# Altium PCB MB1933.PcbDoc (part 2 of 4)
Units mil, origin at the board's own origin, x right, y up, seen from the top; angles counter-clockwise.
Board outline 2755.91 x 3937.01 mil, 4 copper layers (Top Layer, GND, POWER, Bottom Layer), stack 60.63 mil thick; 228 components, 185 nets, 918 pads, 786 vias.
Unrouted connection lines stored in the file: 160.
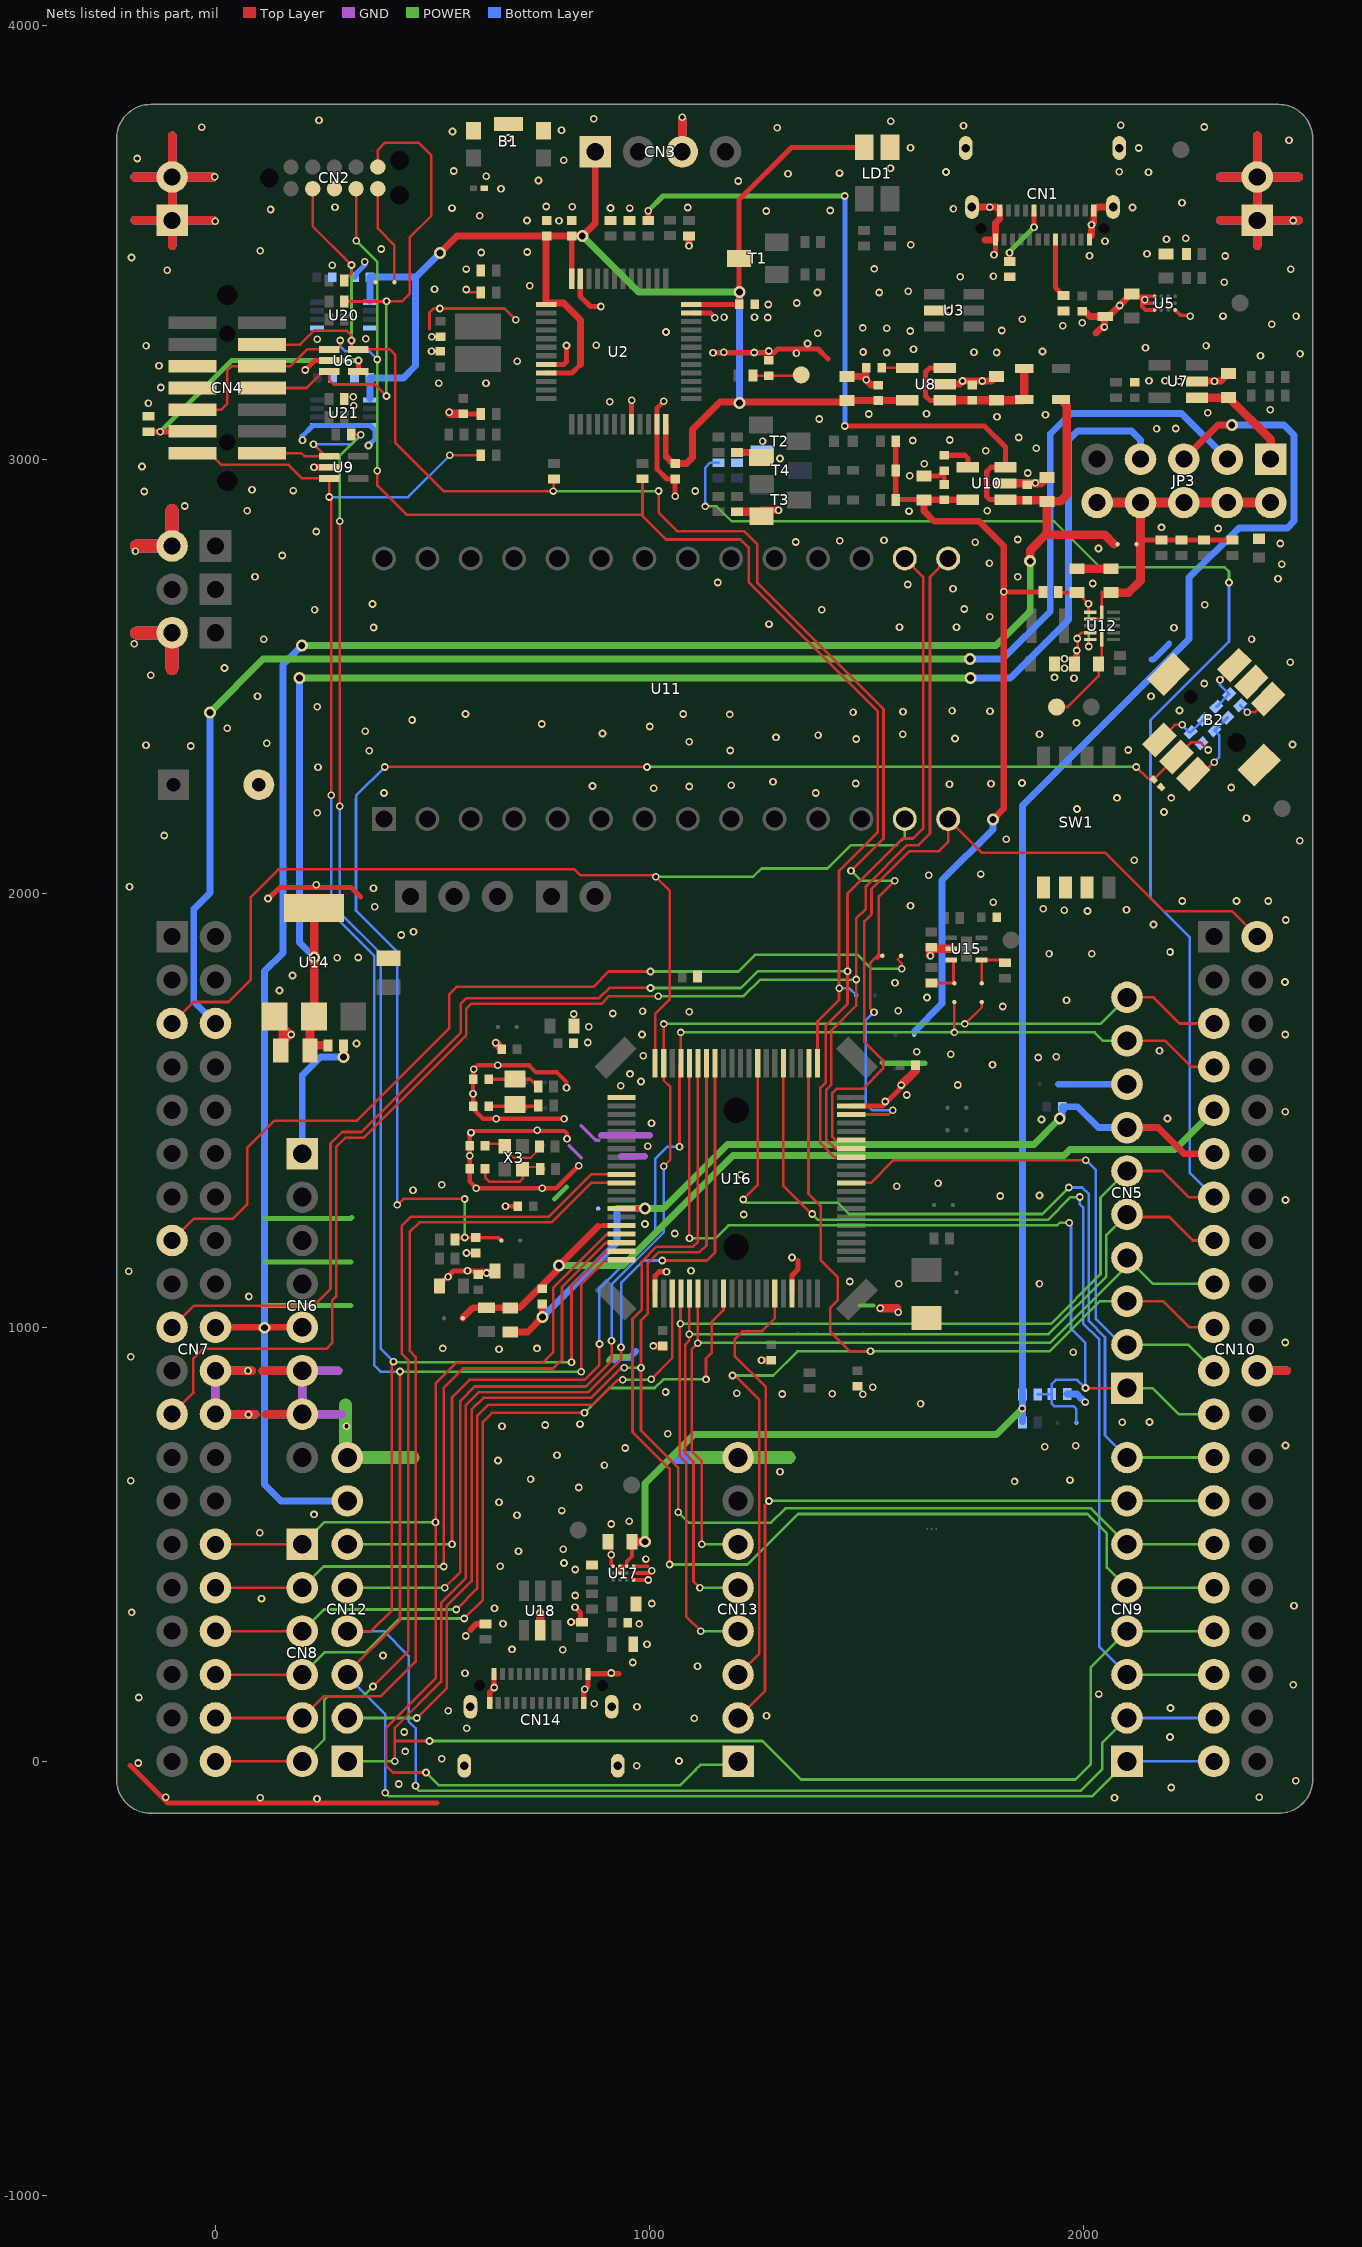
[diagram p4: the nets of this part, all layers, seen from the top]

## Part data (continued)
T1 T2 T3 T4: library part MCD-00073, "NPN Bipolar Transistor", Manufacturer="ON SEMICONDUCTOR", Manufacturer_Part_Number=BSR14, Package=SOT23
TP1 TP2 TP3 TP4 TP5 TP6: library part MCD-00074, "Test Point 1mm", Manufacturer=N/A, Manufacturer_HQ_COO=Unknown
TS1: library part MCD-01194, "-Touch Sensing button: diameter 10mm min,  active shield diameter 12mm min", Manufacturer=N/A, Manufacturer_Part_Number=Touch_sensing_Button
U1 U13: library part MCD-00170, "Diode, ESD TVS, 3V, 100nA, 8V, ST0201", Manufacturer=STMICROELECTRONICS, Manufacturer_HQ_COO=EU, Manufacturer_Part_Number=ESDALC6V1-1U2, Package=ST0201
U2: library part MCD-03056, "MCU, ARM Cortex-M3 32-bit, 128KB Flash, 20KB RAM, No Crypto", Manufacturer=STMICROELECTRONICS, Manufacturer_Part_Number=STM32F103CBT6, Package=LQFP48
U3 U18: library part MCD-00163, "Very low capacitance ESD protection", Manufacturer=STMICROELECTRONICS, Manufacturer_HQ_COO=EU
U4 U19: library part MCD-01207, "Diode, ESD TVS, 22V, 200nA, 25V8, QFN1610", Manufacturer=STMICROELECTRONICS, Manufacturer_HQ_COO=EU, Manufacturer_Part_Number=ESDA25P35-1U1M, Package=QFN1610
U5: library part MCD-03166, "Power switch, 28 V / 5 A  OVP with Low On-resistance, Integrated TVS", Manufacturer="ON SEMICONDUCTOR", Package=WLCSP-12
U6 U9: library part MCD-00136, "Diode, ESD Transil, 3V, 1uA, 7V2, SOT323-5L", Manufacturer=STMICROELECTRONICS, Manufacturer_HQ_COO=EU, Package=SOT323-5
U7: library part MCD-00083, "Enhanced single channel power switches with active low enable pin", Manufacturer=STMICROELECTRONICS, Manufacturer_HQ_COO=EU
U8 U10: library part MCD-00663, "LDO, 200mA, Low quiescent current very low noise LDO", Manufacturer=STMICROELECTRONICS, Manufacturer_HQ_COO=EU, Package=SOT23-5
U11: library part MCD-03134, "Segment LCD, 4 COM, 24 data, DIP28 package", Manufacturer=HZDSLCD, Package=DIP28
U12: library part MCD-03133, "400mA Nano-Quiescent Step down converter with Aux switch", Manufacturer=STMICROELECTRONICS, Manufacturer_Part_Number=ST1PS03AQTR, Package=TQFN12
U14: library part MCD-00088, "IC REG LDO 5V 0.8A SOT223", Manufacturer=STMICROELECTRONICS, Manufacturer_HQ_COO=EU, Package=SOT-223
U15: library part MCD-02159, "MEMS, Low-voltage, ultra-low-power, 0.5°C accuracy I2C/SMBus 3.0 temperature sensor", Manufacturer=STMICROELECTRONICS, Manufacturer_HQ_COO=EU, Package=UDFN-6
U16: library part MCD-03131, "Arm® Cortex®-M0+ 32-bit MCU,  256K Flash memory, with LQFP80 socket footprint (IC149-080-130-B5)", Manufacturer=STMICROELECTRONICS, Package=LQFP80
U17: library part MCD-03166, "Power switch, 28 V / 5 A  OVP with Low On-resistance, Integrated TVS", Manufacturer="ON SEMICONDUCTOR", Manufacturer_Part_Number=FPF3380UCX, Package=WLCSP-12
U20 U21: library part MCD-00264, "IC, 5 Dual-Bit Dual-Supply bus transceiver with configurable voltage translation and 3-State outputs", Manufacturer="TEXAS INSTRUMENTS", Package=VSSOP-8
X1: library part MCD-00092, "Crystal, 8MHz, 8pF, +/-20ppm, 500R, 3.2x2.5mm", Manufacturer=NDK, Manufacturer_Part_Number=NX3225GD-8MHZ-EXS00A-CG04874, Package=3.2x2.5mm
X2: library part MCD-01479, "Crystal, 32.768kHz, 6pF, +/-20ppm, 80K, 2.05x1.2mm", Manufacturer=NDK, Manufacturer_Part_Number=NX2012SA-32.768KHZ-EXS00A-MU00527, Package=2.05x1.2mm
X3: library part MCD-01036, "Crystal, 24MHz, 6pF, +/-20ppm, 80R, 2x1.6mm", Manufacturer=NDK, Manufacturer_Part_Number=NX2016SA-24MHZ-EXS00A-CS10820, Package=2x1.6mm

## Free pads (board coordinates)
  round 11.81 on Mech16 mask+1.97: 0(-227.95,-119.75) 0(-227.95,3817.26) 0(2527.96,-119.75) 0(2527.96,3817.26) 2(-96.85,2275)
  oval 31.5x55.12 on Top Paste mask+1.97: 0(573.23,-10.04) 0(587.4,125.79) 0(912.6,125.79) 0(926.77,-10.04) 0(1728.5,3716.77) 0(1742.68,3580.94) 0(2067.87,3580.94) 0(2082.05,3716.77)
  round 20 on Mech16: 1(136.26,-962.54) 1(2059.39,-962.54)

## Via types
v1: diameter 17.72, hole 9.84, Top Layer to Bottom Layer, tented both sides, 740 vias
v2: diameter 27.56, hole 15.75, Top Layer to Bottom Layer, tented both sides, 45 vias
v3: diameter 19.68, hole 11.81, Top Layer to Bottom Layer, tented both sides, 1 vias

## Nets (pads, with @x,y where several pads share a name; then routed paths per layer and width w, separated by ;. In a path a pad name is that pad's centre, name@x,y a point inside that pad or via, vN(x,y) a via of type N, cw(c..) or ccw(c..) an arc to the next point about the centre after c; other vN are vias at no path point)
3V3: C20.2 C22.2 R32.2 R36.2 R39.2 R44.1 SB14.1 U10.5 | length 1846
  Top Layer w11.81: R39.2@1567.33,2897.77 R39.2@1567.33,2906.68 ; R32.2@1567.33,3041.28 R39.2@1567.33,2906.68 ; C20.2@1632,2906.68 R39.2@1567.33,2906.68 ; v1(1816,2694.28) R44.1@1906.28,2694.28
  Top Layer w15.75: C20.2@1632,2906.04 1632,2880.84 1655.86,2856.98 1759.11,2856.98 1816,2800.09 v1(1816,2694.28) 1816,2195 v2(1791,2170) ; C20.2@1632,2906.68 U10.5@1733.22,2906.68
  Bottom Layer w15.75: 1610.15,1681.73 1674,1745.59 1674,2030 1791,2147 v2(1791,2170)
3V3_STLK: C1.1 C2.1 C6.1 C13.2 C16.2 C19.1 C54.2 C56.2 CN3.1 LD1.4 T1.3 U2.1 U2.9 U2.24 U2.36 U2.48 U8.5 U20.1 U21.1 | length 3861.4
  Top Layer w11.81: U2.9@761.68,3198.79 821.59,3198.79 840.56,3217.75 ; C1.1@761.68,3513.16 C1.1@762.8,3514.28 ; U2.48@820.73,3415.32 820.73,3514.02 C2.1@821,3514.28 ; U2.24@1037.27,3080.68 1037.27,3004.21 1051.51,2989.97 1057.12,2989.97 1039.67,3007.42 ; U2.36@1096.32,3356.27 C6.1@1206.73,3356.27 ; C6.1@1206.37,3357.78 1206.37,3597.74 1326.87,3718.23 LD1.4@1494.62,3718.23
  Top Layer w15.75: v2(516.96,3474.69) 556.55,3514.28 C1.1@762.8,3514.28 C2.1@821,3514.28 v2(845.06,3514.28) 874.96,3544.18 CN3.1@874.96,3708.25 ; C1.1@761.68,3513.16 761.68,3359.68 801.58,3359.68 840.56,3320.71 840.56,3217.75 ; C19.1@1058.96,2989.97 1085.51,2989.97 1098.83,3003.29 1098.83,3068.05 1162.1,3131.32 1455.16,3131.32 C13.2@1455.16,3135.57 1455.26,3135.47 U8.5@1593.45,3135.47
  POWER w15.75: v2(845.06,3514.28) 974.37,3384.98 v2(1206.9,3384.98)
  Bottom Layer w13.78: U20.1@356,3364.6 U20.1@356.21,3364.82
  Bottom Layer w15.75: U21.1@356,3139.41 356,3187.25 432.96,3187.25 460.93,3215.23 460.93,3419.35 ; U20.1@356,3364.6 356,3419.14 C54.2@356.21,3419.35 460.93,3419.35 ; U20.1@356.21,3364.82 356.21,3407.33 ; v2(516.96,3474.69) 461.61,3419.35 460.93,3419.35 ; v2(1206.9,3129.17) v2(1206.9,3384.98)
5V: C21.2 C23.2 CN6.5 CN7.20 CN12.7 D2.1 R4.2 SB2.2 U10.1 U10.3 | length 6505.5
  Top Layer w11.81: R4.2@997,3549.72 v1@997,3572.13 ; v1(1449.52,3076.61) 1771.17,3076.61 1819.84,3027.94 U10.3@1819.84,2981.48 1786.47,2981.48 1776.88,2971.89 1776.88,2914.01 1784.21,2906.68 U10.1@1819.84,2906.68
  Top Layer w15.75: CN7.20@0,1000 CN6.5@200,1000
  Top Layer w19.68: U10.1@1819.84,2906.68 1821.06,2905.46 1915.53,2905.46 C21.2@1918.19,2902.79 ; v2(1877,2765) 1877,2790.16 1912.49,2825.65 ; C21.2@1920.99,2900 C21.2@1918.19,2902.79 ; D2.1@1947.59,3137.73 1961,3124.32 1961,2917.68 1946.12,2902.79 C21.2@1918.19,2902.79 ; 2070.18,2804 2048.53,2825.65 1912.49,2825.65 ; 1912.49,2825.65 1915.56,2828.72 C21.2@1915.56,2902.79 C21.2@1918.19,2902.79
  POWER w11.81: v1(997.05,3572.18) 1031.01,3606.14 v1(1450.01,3606.14)
  POWER w15.75: v2(198.92,2570.41) 1798.53,2570.41 1877,2648.88 v2(1877,2765)
  Bottom Layer w11.81: v1(1450.01,3606.14) 1450.2,3605.94 v1@1450.2,3076.61
  Bottom Layer w15.75: v2(198.92,2570.41) 155.22,2526.71 155.22,1862.44 113.2,1820.41 v2(113.2,998.95) 113.2,638.03 151.23,600 CN12.7@300,600
5V_LP: C25.2 JP3.2 JP3.4 JP3.6 JP3.8 JP3.10 R40.1 R41.1 R42.1 R43.1 SB2.1 U12.2 U12.12 | length 959.8
  Top Layer w5.98: U12.2@2015.43,2631.75 2036.1,2631.75 2042,2637.65 U12.12@2042,2646.51 2042,2694.28
  Top Layer w11.81: 2132.28,2813.72 R40.1@2225,2813.72 R42.1@2343,2813.72
  Top Layer w19.68: C25.2@2058.96,2692.63 2103.71,2692.63 2131,2719.93 JP3.8@2131,2900
  Top Layer w23.62: JP3.10@2031,2900 JP3.8@2131,2900 JP3.6@2231,2900 JP3.4@2331,2900 JP3.2@2431,2900
5V_STLK: C11.2 JP3.1 U7.1 | length 255
  Top Layer w19.68: U7.1@2261.17,3141.57 C11.2@2333.51,3141.57 ; C11.2@2333.81,3142.36 2431,3045.17 JP3.1@2431,3000
5V_USB: C51.2 JP3.5 R72.2 R73.2 U17.A2 U17.A3 U17.B2 | length 4091.9
  Top Layer w8.66: U17.B2@931.77,433.75 U17.A2@931.77,449.5 U17.A3@947.52,449.5 947.52,460.52 959.56,472.56 C51.2@959.56,506
  Top Layer w15.75: JP3.5@2231,3000 2310,3079 v2(2341.34,3079)
  Top Layer w19.68: C51.2@959.56,506 v2(989.38,506)
  POWER w15.75: v2(989.38,506) 989.38,640.18 1102.2,753 1798.8,753 v1(1858.7,812.9)
  Bottom Layer w15.75: R73.2@1858.98,782.4 R72.2@1858.98,845.6 1858.98,2201.98 2243,2586 2243,2727 2357.73,2841.73 2469.19,2841.73 2485,2857.54 2485,3055.27 2461.27,3079 v2(2341.34,3079)
5V_VIN: C32.2 JP3.7 R51.1 U14.2 U14.4 | length 3499.3
  Top Layer w15.75: C32.2@217.72,1637.54 C32.2@217.72,1649.55 ; U14.2@217.72,1706.83 U14.2@227.07,1716.18
  Top Layer w19.68: U14.2@217.72,1706.83 217.72,1649.55 R51.1@258.77,1649.55 ; U14.2@227.07,1716.18 U14.4@227.07,1966.18
  POWER w15.75: v2(193.51,2496) v2(1739.57,2496)
  Bottom Layer w15.75: v2(193.51,2496) 193.51,1886.36 v2(227.57,1852.3) ; v2(1739.57,2496) 1831.1,2496 1965.07,2629.97 1965.07,3043.64 1985.93,3064.51 2110.74,3064.51 2131,3044.24 JP3.7@2131,3000
AGND: C46.1 C47.2 C58.1 CN5.7 CN10.11 SB21.2 U16.14 | length 2024.8
  Top Layer w12.6: U16.14@935.23,1273.62 v2@985.76,1273.62
  Top Layer w13.78: v2@985.76,1273.62 v2@989.38,1270
  Top Layer w15.75: C47.2@679,989.51 719.4,989.51 v2(753.75,1023.86) ; v2@753.26,1024.35 C46.1@753.26,1053.68 ; CN5.7@2100,1460 2171.44,1460 2231.44,1400 CN10.11@2300,1400
  POWER w15.75: v2(989.38,1273.6) 1031.66,1273.6 1179.39,1421.33 1885.33,1421.33 v2(1945,1481)
  Bottom Layer w15.75: v2(753.75,1023.86) 924.91,1195.02 SB21.2@924.91,1273.56 v2(989.38,1273.6) ; v2@988.8,1269.43 v2@989.38,1270 ; v2(1945,1481) 1950.72,1486.72 C58.1@1950.72,1508 ; C58.1@1950.72,1508.11 1985.93,1508.11 2034.04,1460 CN5.7@2100,1460
ARD_A0: CN7.30 CN8.1 CN13.1 U16.17 | length 2967.5
  Top Layer w5.98: CN7.30@0,500 CN8.1@200,500 ; v1(485,-25.59) 408.59,-25.59 393,-10 393,77.08 507,191.08 v1(507,551) 507,871 554,918 753.82,918 777.86,942.04 777.86,1090.88 901.54,1214.56 U16.17@935.23,1214.56
  POWER w5.98: CN8.1@200,500 251,551 v1(507,551) ; v1(485,-25.59) 514.22,-54.81 1071.19,-54.81 1106.15,-19.85 1106.15,-19.19 1117.19,-8.15 1200,-8.15 CN13.1@1200,0
ARD_A1: CN7.32 CN8.2 U16.18 | length 1605.6
  Top Layer w5.98: CN7.32@0,400 CN8.2@200,400 ; v1(526,449) 526,860.91 570.1,905.02 777.54,905.02 798.24,925.71 798.24,1092.9 900.22,1194.88 U16.18@935.23,1194.88
  POWER w5.98: CN8.2@201.34,398.66 CN8.2@200,400 249,449 v1(526,449)
ARD_A2: CN7.34 CN8.3 U16.23 | length 1697.7
  Top Layer w5.98: CN7.34@0,300 CN8.3@200,300 ; v1(555,350) 602.95,397.95 602.95,795.95 629.03,822.03 869.37,822.03 926.43,879.1 v1(938.1,879.1) ; v1(1003.7,880.2) 1052.22,928.72 1052.22,1077.62 U16.23@1052.36,1077.76
  POWER w5.98: CN8.3@200,300 250,350 v1@553,350 ; v1@555,348 v1@553,350 ; v1(555,350) v1@553,350 ; v1(938.1,879.1) 1002.6,879.1 v1(1003.7,880.2)
ARD_A3: CN7.36 CN8.4 U16.29 | length 1866.8
  Top Layer w5.98: CN7.36@0,200 CN8.4@200,200 ; v1(573,329.19) 616,372.19 616,781.9 637.1,803 v1(849.96,803) ; v1(1130,880) 1130,928.2 1143.06,941.26 1143.06,1011.94 1170.47,1039.34 U16.29@1170.47,1077.76
  POWER w5.98: CN8.4@200.45,199.55 CN8.4@200,200 251,251 346,251 424.19,329.19 v1(573,329.19) ; v1(849.96,803) 907.21,860.25 1011.95,860.25 1031.7,880 v1(1130,880)
ARD_A4: CN7.38 CN8.5 U16.11 | length 2044.4
  Top Layer w5.98: CN7.38@0,100 CN8.5@200,100 250.33,150.33 381.33,150.33 461.04,230.04 461.04,931.96 448,945 448,1220.35 469.57,1241.92 774.57,1241.92 865.32,1332.67 U16.11@935.23,1332.67
ARD_A5: CN7.40 CN8.6 U16.10 | length 2143.7
  Top Layer w5.98: CN7.40@0,0 CN8.6@200,0 ; v1(363,172.56) 443.85,253.41 443.85,925.15 428.85,940.15 428.85,1232.85 450.9,1254.9 767.87,1254.9 865.32,1352.36 U16.10@935.23,1352.36
  POWER w5.98: CN8.6@200,0 251,51 251,142 259.33,150.33 340.77,150.33 v1(363,172.56)
ARD_D0: CN4.13 CN9.1 CN10.39 CN12.3 R33.2 U9.3 U16.20 | length 6631.5
  Top Layer w5.98: CN4.13@-53,3014 -13.76,3014 13.39,2986.85 168.51,2986.85 199.7,2955.66 U9.3@262.5,2955.66 v1@262.5,2912.5 ; v1(267,2226) 262.04,2226 267,2230.96 267,2908 v1@262.5,2912.5 ; CN12.3@300,200 425,325 v1(425,898) ; v1(540,3009) R33.2@611.28,3009 ; v1@842.71,898 842.71,1099.47 898.74,1155.51 U16.20@935.23,1155.51 ; v1@262.5,2912.5 262.5,2911.47 262,2911.96 v1(262,2913) v1@262.5,2912.5
  POWER w5.98: v1(262,2913) 262.19,2913 v1@262.51,2912.68 ; v1(391,-72) 399.78,-80.78 425.78,-80.78 2019.22,-80.78 CN9.1@2100,0 ; v1(425,898) 842.5,898 v1@842.72,897.77
  Bottom Layer w5.98: v1@262.51,2912.68 443.68,2912.68 v1(540,3009) ; v1(267,2226) 267,1954 365.85,1855.15 365.85,912.15 380,898 v1(425,898) ; CN12.3@300,200 391,109 v1(391,-72) ; v1@842.72,897.77 v1(842.82,897.87) ; CN9.1@2100,0 CN10.39@2300,0
ARD_D1: CN4.14 CN9.2 CN10.37 CN12.4 R27.2 U9.1 U16.19 | length 6404.8
  Top Layer w5.98: CN4.14@107,3014 197.46,3014 204.62,3006.84 U9.1@253.44,3006.84 ; v1(225.88,3034.4) U9.1@253.44,3006.84 ; U9.1@262.5,3006.84 U9.1@253.44,3006.84 ; v1@286,2200.36 v1(286,2857) ; CN12.4@300,300 358,300 406.15,348.15 v1@406.15,921 ; R27.2@313.69,3057.22 314.77,3056.14 v1(334.85,3056.14) ; U16.19@935.23,1175.19 900.06,1175.19 820.24,1095.37 v1@820.24,919.92 ; v1@820.24,919.92 819.94,919.62 v1(820.24,919.62) v1@820.24,919.92
  POWER w5.98: v1(286,2857) 286,3007.29 v1(334.85,3056.14) ; v1(410,921) 411.38,919.62 v1(820.24,919.62) ; v1(461,-56) 461,-60 468.79,-67.79 1993.21,-67.79 2043,-18 2043,43 CN9.2@2100,100
  Bottom Layer w5.98: v1(225.88,3034.4) 313.11,3034.4 v1(334.85,3056.14) ; v1(286.03,2200.33) 286.03,1956.04 380.32,1861.75 380.32,950.68 v1(410,921) ; CN12.4@300,300 388,300 445.15,242.85 445.15,92.19 461,76.34 v1(461,-56) ; CN9.2@2099.25,99.25 CN9.2@2100,100 CN10.37@2300,100
ARD_D2: CN9.3 CN10.35 U16.65 | length 2365.2
  Top Layer w5.98: U16.65@1308.26,1608.26 1308.26,1325.74 1374,1260 v1(1375,1261)
  POWER w5.98: v1(1375,1261) 1388.28,1247.72 1917.59,1247.72 1969.87,1300 v1(1991,1300) ; CN9.3@2100,200 CN10.35@2300,200
  Bottom Layer w5.98: v1(1991,1300) 1991,1284 1999.02,1275.98 1999.02,1008.62 2036.22,971.42 2036.22,263.78 CN9.3@2100,200
ARD_D3: CN9.4 CN10.33 CN12.1 U16.73 | length 4459.9
  Top Layer w5.98: v1(413,0) 413,48 ; v1(493,47) 414,47 413,48 ; v1(934.4,954) 934.4,926.07 858.97,850.64 607.05,850.64 576.98,820.57 576.98,422 519.98,365 519.98,183.98 413,77 413,48 ; v1(1029,1154) 1132.09,1154 1150.78,1172.69 U16.73@1150.78,1608.26 ; CN9.4@2097.38,297.38 CN9.4@2100,300
  POWER w5.98: CN12.1@300,0 v1(413,0) ; v1(493,47) 1260,47 1348.82,-41.82 1981.18,-41.82 2016.02,-6.98 2016.02,216.02 CN9.4@2100,300 CN10.33@2300,300
  Bottom Layer w5.98: v1(934.4,954) 934.4,1102.04 986.36,1154 v1(1029,1154)
ARD_D4: CN9.5 CN10.31 U16.75 | length 2720.5
  Top Layer w5.98: v1(1046.2,453.59) 1046.2,673.8 960.7,759.3 960.7,1019.49 982.1,1040.89 982.1,1152.12 1015.98,1186 1077.34,1186 ; 1077.36,1185.98 1100.64,1185.98 1111.41,1196.76 U16.75@1111.41,1608.26
  POWER w5.98: v1(1046.2,453.59) 1225.59,453.59 1342,570 2008.43,570 2053.59,524.84 2053.59,446.41 CN9.5@2100,400 CN10.31@2300,400
ARD_D5: CN9.6 CN10.29 CN12.2 U16.74 | length 3835.9
  Top Layer w5.98: v1(464,100) 533,169 533,358.69 589.97,415.66 589.97,810.31 617.31,837.66 865.16,837.66 934.1,906.6 v1(941.7,906.6) ; v1(1066,574) 1066,677 980.23,762.77 v1(980.23,906.6) 980.23,1015.89 996.09,1031.75 996.09,1147.75 1021.34,1173 1115.29,1173 1131.1,1188.81 U16.74@1131.1,1608.26
  POWER w5.98: CN12.2@300,100 v1(464,100) ; v1(941.7,906.6) v1(980.23,906.6) ; v1(1066,574) 1090,550 1280,550 1313,583 2017,583 CN9.6@2100,500 CN10.29@2300,500
ARD_D6: CN9.7 CN10.27 CN13.2 U16.35 | length 2131.5
  Top Layer w5.98: CN13.2@1200,100 CN13.2@1201.97,101.97 ; CN13.2@1203.94,100 1265.98,162.05 1265.98,590.98 v1(1275,600) 1268,607 1268,862.1 1196.18,933.92 1196.18,972.18 1215.38,991.38 1259.08,991.38 1288.58,1020.87 U16.35@1288.58,1077.76
  POWER w5.98: v1(1275,600) CN9.7@2100,600 CN10.27@2300,600
ARD_D7: CN9.8 CN10.25 U16.68 | length 2012.8
  Top Layer w5.98: v1(1215.65,1294.35) 1249.21,1327.92 U16.68@1249.21,1608.26
  POWER w5.98: v1(1215.65,1294.35) 1223,1287 1433,1287 1459,1261 1905,1261 v1(1966,1322) ; CN9.8@2100,700 CN10.25@2300,700
  Bottom Layer w5.98: v1(1966,1322) 1996.78,1322 2012,1306.78 2012,1014 2049.2,976.8 2049.2,750.8 CN9.8@2100,700
ARD_D8: CN5.1 CN10.23 R71.2 R72.1 SB24.1 U16.76 | length 2272.2
  Top Layer w5.98: U16.76@1091.73,1608.26 1091.73,1204.27 1092,1204.54 v1(1092,1205) ; v1(2004.16,860) CN5.1@2100,860
  POWER w5.98: v1(1092,1205) 1152,1205 1181.73,1234.73 1938.73,1234.73 1945,1241 v1(1967,1241) ; CN5.1@2100,860 2158.85,860 2218.85,800 CN10.23@2300,800
  Bottom Layer w5.98: R72.1@1894.42,845.6 1926.12,845.55 R71.2@1926.57,846 ; v1(1967,1241) 1970.85,1237.15 1970.85,997.15 2004.16,963.84 v1(2004.16,860) 1985.16,879 1936,879 1926.57,869.57 R71.2@1926.57,846 ; SB24.1@1983.28,780.3 1983.28,811.41 1976.2,818.5 1932,818.5 1926.57,823.93 R71.2@1926.57,846
ARD_D9: CN5.2 CN10.21 U16.50 | length 1259.1
  Top Layer w5.98: U16.50@1464.76,1332.67 1510.03,1332.67 1562.36,1385 v1(2005,1385)
  POWER w5.98: CN5.2@2100,960 2240,960 CN10.21@2300,900
  Bottom Layer w5.98: v1(2005,1385) 2005.7,1385 2028.26,1362.45 2028.26,1018.85 2087.11,960 CN5.2@2100,960
ARD_D10: CN5.3 CN10.19 CN13.3 U16.62 | length 2711.8
  Top Layer w5.98: v1(1191,889) 1197,889 1253,833 1253,249.06 CN13.3@1203.94,200 ; CN13.3@1200,200 CN13.3@1201.97,201.97 ; U16.62@1367.32,1608.26 1366.15,1607.09 1366.15,1307.46 1394,1279.61 1394,1155.27 1434,1115.27 1434,1063 1416,1045 1416,990.52 1461.85,944.67 v1(1509,944.67) ; CN5.3@2100,1060 2183.72,1060 2243.72,1000 CN10.19@2300,1000
  POWER w5.98: v1(1191,889) 1285,889 1340.67,944.67 v1(1509,944.67) 1921.67,944.67 2037,1060 CN5.3@2100,1060
ARD_D11: CN5.4 CN10.17 CN13.6 U16.26 | length 1975.6
  Top Layer w5.98: v1(1111.23,963.52) 1097.04,949.33 1097.04,714.96 1120,692 v1(1120,500) ; v1@1111.29,963.52 U16.26@1111.29,1077.76
  POWER w5.98: v1(1111.23,963.52) 1112.36,964.66 1923.29,964.66 2106,1147.36 CN5.4@2106,1154 ; v1(1120,500) CN13.6@1199.96,500 ; CN5.4@2100,1160 CN5.4@2106,1154 ; CN10.17@2300,1100 2160,1100 CN5.4@2106,1154
ARD_D12: CN5.5 CN10.15 CN13.5 U16.25 | length 2186.3
  Top Layer w5.98: v1(1091.35,984.29) 1091.35,969.35 1082.28,960.28 1082.28,708.85 1101.15,689.98 1101.15,414.85 v1(1116,400) ; v1(1091.35,984.29) U16.25@1091.37,1077.76 ; CN5.5@2100,1260 2100,1254.15 2197.46,1254.15 2251.61,1200 CN10.15@2300,1200
  POWER w5.98: v1(1091.35,984.29) 1091.39,984.34 1919.35,984.34 2052.56,1117.54 2052.56,1212.56 CN5.5@2100,1260 ; v1(1116,400) CN13.5@1199.98,400
ARD_D13: CN5.6 CN10.13 CN13.4 R66.1 U16.24 | length 5354.3
  Top Layer w5.98: v1(1071.07,1007.91) 1069.29,1006.14 1069.29,703.47 1084.85,687.91 1084.85,333.15 v1(1118,300) ; v1@1071.2,1007.91 1071.2,1076.91 U16.24@1072.04,1077.76 ; CN5.6@2100,1360 2182,1360 2242,1300 CN10.13@2300,1300
  POWER w5.98: v1(1071.07,1007.91) 1924.56,1007.91 2039,1122.35 2039,1299 CN5.6@2100,1360 ; v1(1118,300) CN13.4@1200,300 ; v1(1128.45,2891.18) 1154.82,2891.18 1189.02,2856.98 1931.69,2856.98 2037.67,2751 2325,2751 2334.97,2741.03 v1(2334.97,2716.06)
  Bottom Layer w5.98: v1(1128.45,2891.18) 1128.45,2980.62 1139.7,2991.88 R66.1@1159.35,2991.88 ; CN10.13@2300,1300 2244.69,1355.31 2244.69,1898.31 2154.04,1988.96 2154.04,2398.68 2334.97,2579.6 v1(2334.97,2716.06)
ARD_D14: CN5.9 CN10.7 CN12.6 SB4.1 U16.77 | length 3147.3
  Top Layer w5.98: v1@545,499 v1(545,500) 545,838.83 585.17,879 850.61,879 884.55,912.95 v1(884.55,961.55) ; v1(1069,1416) 1069,1605.22 U16.77@1072.04,1608.26 v1(1072.05,1679.42) ; v1(1702.28,1679.42) SB4.1@1702.28,1749.26 ; CN5.9@2100,1660 2188.47,1660 2248.47,1600 CN10.7@2300,1600
  POWER w5.98: CN12.6@300,500 CN12.6@303.94,500 v1(545,500) ; v1(1072.05,1679.42) v1(1702.28,1679.42) 2025.35,1679.42 2044.77,1660 CN5.9@2100,1660
  Bottom Layer w5.98: v1@884.55,960.67 v1(884.55,961.55) 884.55,1089.84 1013,1218.28 1013,1263.6 1013.15,1263.75 1013.15,1283.45 1013,1283.6 1013,1388 1041.04,1416.04 1041.07,1416 v1(1069,1416)
ARD_D15: CN5.10 CN10.5 CN12.5 SB5.1 U16.79 | length 3283.3
  Top Layer w5.98: v1(528,400) 564,436 564,830.36 597.27,863.62 853.6,863.62 912.51,922.54 v1(912.51,968.84) ; v1(1032.67,1371) 1047.9,1386.23 1047.9,1553.93 1032.67,1569.16 U16.79@1032.67,1608.26 1032.67,1698.67 v1(1033,1699) ; v1(1726,1699) 1727,1699 1765.32,1737.32 SB5.1@1765.32,1749.21 ; CN5.10@2100,1760 2160.96,1760 2220.96,1700 CN10.5@2300,1700
  POWER w5.98: CN12.5@300,400 CN12.5@303.94,400 v1(528,400) ; v1(1033,1699) v1(1726,1699) 2039,1699 CN5.10@2100,1760
  Bottom Layer w5.98: v1(912.51,968.84) 912.51,1098.51 1033,1219 v1@1033,1371
AVDD: C46.2 C47.1 CN10.9 R59.2 SB12.2 U16.16 | length 2122.2
  Top Layer w11.81: 892.19,1234.25 U16.16@935.23,1234.25
  Top Layer w15.75: SB12.2@569.62,1021 593.71,1045.09 R59.2@624.37,1045.09 ; R59.2@604.93,1045.21 701.09,1045.21 791.54,1135.67 v2(791.54,1142.36) ; v2@791.49,1142.41 881.31,1232.22
  POWER w15.75: v2(791.54,1142.36) 939.11,1142.36 1192.63,1395.88 1954.88,1395.88 1969,1410 2210,1410 CN10.9@2300,1500
COM0: CN7.19 U11.16 U16.53 | length 3691.6
  Top Layer w5.98: CN7.19@-100,1000 -50.36,1049.64 225.96,1049.64 265,1088.69 265,1423 292.05,1450.05 336.41,1450.05 564.74,1678.38 564.74,1745 578.08,1758.34 883.61,1758.34 907.39,1782.11 v1@1002,1782.11 ; U16.53@1464.76,1391.73 1426.27,1391.73 1393.42,1424.58 1393.42,1551.79 1406.02,1564.38 1406.02,1695.02 1456,1745 v1(1456,1820) 1456,1999 1583,2126 1607,2126 1630.16,2149.16 1630.16,2728.84 U11.16@1588,2771
  POWER w5.98: v1(1002,1781.77) 1210.77,1781.77 1249,1820 v1(1456,1820)
COM1: CN7.23 U11.15 U16.54 | length 3868.5
  Top Layer w5.98: CN7.23@-100,800 -50.55,849.45 -51,849.89 -51,927.67 -27.67,951 256.45,951 269,963.55 269,1061.45 278,1070.45 278,1415.28 298.97,1436.25 340.97,1436.25 578.08,1673.35 578.08,1734.27 589.16,1745.35 888.99,1745.35 906.56,1762.92 v1(1020,1762.92) ; U16.54@1464.76,1411.41 1428.59,1411.41 1407,1433 1407,1547 1419,1559 1419,1683.78 1476,1740.78 v1(1476,1801.15) 1476,1941.34 1498.34,1963.68 1498.34,2015.77 1593.57,2111 1619.55,2111 1646,2137.45 1646,2729 U11.15@1688,2771
  POWER w5.98: v1(1020,1762.92) 1216.91,1762.92 1255.13,1801.15 v1(1476,1801.15)
COM2: CN10.2 U11.14 U16.55 | length 1825.4
  Top Layer w5.98: U16.55@1464.76,1431.1 1428.61,1431.1 1421,1438.71 1421,1540 1430.55,1549.55 1491.55,1549.55 1538.02,1596.02 1538.02,1614.74 1495,1657.76 1495,1935 1511.33,1951.33 1511.33,2009.33 1599,2097 1667.27,2097 1688,2117.73 U11.14@1688,2171 1766,2093 2050,2093 2184.34,1958.66 2341.34,1958.66 CN10.2@2400,1900
COM3: CN7.5 U11.13 U16.80 | length 2489.7
  Top Layer w5.98: CN7.5@-100,1700 -50.45,1749.55 29.93,1749.55 81.67,1801.28 81.67,1991.83 144.93,2055.09 826.61,2055.09 840.7,2041 1011,2041 v1(1014,2038) 1046.15,2005.85 1046.15,1755.08 1012.99,1721.92 U16.80@1012.99,1608.26
  POWER w5.98: v1(1014,2038) 1238.85,2038 1257.85,2057 1410,2057 1464,2111 1569.11,2111 1588,2129.89 U11.13@1588,2171
E5V: CN7.6 JP3.3 | length 3679.1
  Top Layer w15.75: CN7.6@0,1700 CN7.6@14.24,1700
  POWER w15.75: v2(-13,2416.55) 109.85,2539.41 v2(1738.39,2539.41)
  Bottom Layer w15.75: v2(-13,2416.55) -13,2001 -50,1964 -50,1750 CN7.6@0,1700 ; v2(1738.39,2539.41) 1813.39,2539.41 1923.14,2649.15 1923.14,3057.62 1970.87,3105.35 2225.65,3105.35 JP3.3@2331,3000
GND: B1.1 B1.3 B1.5 B2.5 B2.7 B2.8 C1.2 C2.2 C3.2 C4.1 C5.2 C6.2 C7.1 C8.2 C9.1 C10.1 C11.1 C12.1 C13.1 C14.1 C15.1 C16.1 C17.1 C18.1 C19.2 C20.1 C21.1 C22.1 C23.1 C24.1 C25.1 C26.1 C27.1 C28.2 C29.1 C30.1 C31.1 C32.1 C33.1 C34.1 C35.1 C36.1 C37.1 C38.1 C39.1 C40.1 C41.1 C42.2 C43.1 C44.1 C45.2 C48.1 C49.1 C50.2 C51.1 C52.2 C53.2 C54.1 C55.2 C56.1 C57.2 CN1.A1 CN1.A12 CN1.B1 CN1.B12 CN1.SH1 CN1.SH2 CN1.SH3 CN1.SH4 CN2.3 CN3.3 CN4.5 CN4.7 CN6.6 CN6.7 CN7.22 CN7.24 CN10.22 CN11.2 CN12.8 CN13.8 CN14.A1 CN14.A12 CN14.B1 CN14.B12 CN14.SH1 CN14.SH2 CN14.SH3 CN14.SH4 JP1.1 JP1.2 JP2.1 JP2.2 JP4.2 LD1.3 LD6.2 R2.1 R3.2 R5.1 R9.1 R10.2 R11.2 R15.2 R16.2 R23.2 R24.2 R26.1 R31.1 R38.1 R47.1 R50.2 R61.1 R63.2 R64.2 R65.1 R71.1 SB1.1 SB21.1 SW1.1 SW1.2 SW1.3 T2.2 T3.2 T4.2 U1.2 U2.8 U2.20 U2.23 U2.35 U2.47 U3.2 U4.2 U5.A1 U5.A4 U5.B4 U5.C4 U6.2 U7.2 U8.2 U9.2 U10.2 U12.4 U13.2 U14.1 U15.5 U16.1 U16.21 U16.37 U16.59 U17.A1 U17.A4 U17.B4 U17.C4 U18.2 U19.2 U20.4 U20.5 U21.4 U21.5 | length 17382.9
  Top Layer w5.98: 493,3299.86 493,3337.33 502.8,3347.13 665.81,3347.13 v1(691.94,3321) ; v1(578,3391) 578,3386.05 579.67,3384.38 R15.2@611.28,3384.38 ; v1@1986.33,2559.09 1986.33,2591.76 1994.82,2600.25 U12.4@2015.43,2600.25
  Top Layer w7.87: v1(578.45,1171.2) C41.1@599.12,1171.2
  Top Layer w8.46: C4.1@2116.37,3375.25 2133.57,3375.25 ; U5.A4@2163.55,3343.76 2142.4,3343.76 2133.57,3352.58 v1@2133.57,3364.1 ; U5.B4@2163.55,3359.51 2138.17,3359.51 v1@2133.57,3364.1 ; U5.C4@2163.55,3375.25 2133.57,3375.25 ; U5.A1@2210.79,3343.76 2223.18,3331.37 v1@2243.08,3331.37 ; v1@2133.57,3364.1 2133.57,3375.25
  Top Layer w8.66: C51.1@904.44,506 911.67,498.77 911.67,453.85 U17.A1@916.02,449.5 ; U17.C4@963.27,418 v1(997,418) ; U17.B4@963.27,433.75 v1@1001.91,433.75 ; U17.A4@963.27,449.5 995.56,449.5
  Top Layer w9.84: C39.1@585.74,1370.22 585.74,1335.67 v1(600.99,1320.41) v1(752.57,1320.41) 785.24,1320.41 v1(837.02,1372.18) ; v1@585.74,1395.61 585.74,1445.81 v1(588.49,1448.56) 592.36,1452.43 803.91,1452.43 810.05,1446.3 v1(810.05,1434.68) ; C39.1@585.83,1370.31 v1(585.83,1395.51) ; v1(593.31,1538.23) C36.1@593.31,1571.1 ; v1@593.9,1535.18 C37.1@593.9,1509.58 593.9,1503.16 616.51,1480.55 v1(646.66,1480.55) ; C36.1@593.9,1571.69 v1@593.9,1593.44 ; v1(595.18,1594.72) 603.96,1603.49 722.55,1603.49 738.71,1587.34 786.6,1587.34 808.57,1565.37 v1@808.57,1549.94 ; v1@646.66,1480.24 v1@803.16,1480.24 ; v1(668.22,1279.17) 668.22,1279.07 C40.1@696.56,1279.07 ; v1@803.16,1479.97 v1(803.16,1480.35)
  Top Layer w11.81: -196.45,-9.21 -110.07,-95.59 510.01,-95.59 ; v1(121.09,1987.73) 122.45,1987.73 147.6,2012.89 312.85,2012.89 334.46,1991.28 ; v1(206.96,3205.25) 228.96,3227.25 U6.2@262.5,3227.25 ; C45.2@510.24,1095.12 513.1,1095.12 545.79,1127.8 545.95,1127.8 548.1,1129.96 C43.1@644.2,1129.96 ; C17.1@571.17,3104.47 611.12,3104.47 R24.2@611.28,3104.3 ; CN14.B12@631.89,134.06 631.89,159.89 641.73,169.73 CN14.A1@641.73,200.98 ; U2.8@761.68,3218.47 802.6,3218.47 808.67,3224.55 v1(808.67,3261.95) ; v1@819.18,320.72 R63.2@844,320.72 841.09,323.62 841.09,342.21 v1(828.3,355) ; U2.47@840.42,3415.32 840.42,3374.98 863.79,3351.61 v1(887.9,3351.61) ; CN14.B1@848.43,134.06 848.43,163.43 v1(851,166) 858.27,173.27 CN14.A12@858.27,200.98 859.28,202 929,202 ; U2.20@958.53,3080.68 958.53,3135.06 v1(959.26,3135.8) ; U16.21@1012.99,1077.76 1012.99,1118.7 1022.29,1128 v1(1039,1128) ; v1(1032.78,3133.4) 1017.58,3118.2 U2.23@1017.58,3080.68 1017.58,2976.85 1039.9,2954.54 C19.2@1058.96,2954.54 v1(1058.96,2914.51) ; U2.35@1096.32,3336.58 1139.84,3336.58 v1(1150.4,3326.02) ; v1(1146.37,3245.21) 1286.72,3245.21 1295.38,3253.88 1388.29,3253.88 1410.74,3231.44 ; U16.37@1327.95,1077.76 1327.95,1119.32 1342.23,1133.6 1342.23,1153.38 ; U16.59@1464.76,1509.84 1537.23,1509.84 1607.49,1580.09 ; C20.1@1632,2961.16 1666.25,2961.16 C18.1@1678.55,2973.46 C22.1@1678.55,2941.81 ; v1@1797.01,3475.09 CN1.A12@1797.01,3505.75
  Top Layer w13.78: 587.4,303.13 600.98,316.72 R64.2@622,316.72
  Top Layer w15.75: C32.1@157.78,1658.01 v1(174.32,1674.55) U14.1@157.78,1691.08 ; v1@228.63,2981.25 U9.2@262.5,2981.25 ; v1(1008.5,957.2) C48.1@1028.35,957.22 ; v1(1090.95,3491.77) R5.1@1091,3514.28 ; R31.1@1201.29,3015.59 1245.12,3015.59 T2.2@1256.83,3003.88 ; T3.2@1257.49,2868.54 1257.49,2882.52 v1(1296.96,2882.52) ; v1(1258,924) 1258.25,924.25 C49.1@1280,924.28 ; C13.1@1455.16,3190.69 v1@1499.26,3190.69 ; C10.1@1499.26,3210.57 v1@1499.26,3190.69 ; C16.1@1526.72,3170.61 1509.69,3170.61 1499.26,3181.04 v1@1499.26,3190.69 ; U3.2@1656.45,3342.75 1690.56,3342.75 v1(1690.66,3342.66) ; U8.2@1680.07,3172.87 1715.58,3172.87 1720.96,3178.25 v1(1720.96,3180.25) 1746.02,3180.25 C15.1@1748.02,3178.25 ; CN1.SH2@1742.68,3580.94 1798.58,3580.94 CN1.B1@1806.85,3572.68 1806.85,3554.03 1797.01,3544.18 CN1.A12@1797.01,3505.75 ; C15.1@1752.41,3179.86 v1(1766.21,3179.86) 1787.94,3179.86 C12.1@1798.96,3190.88 ; 1772.65,3505.16 CN1.A12@1794.89,3505.16 ; C27.1@1983.4,2528.25 1983.4,2546.95 ; C5.2@2002.81,3340.54 2014.7,3328.65 U4.2@2055.81,3328.65 ; CN1.A1@2018.02,3515.59 v1(2018.02,3540.32) 2023.39,3545.69 CN1.B12@2023.39,3572.68 2031.65,3580.94 CN1.SH1@2067.87,3580.94 ; 2028.9,3290.52 2047.96,3309.57 2047.96,3320.8 U4.2@2055.81,3328.65 ; C4.1@2110.81,3380.81 2108.96,3380.81 2056.8,3328.65 U4.2@2055.81,3328.65 ; U7.2@2261.17,3179.86 2316.19,3179.86 C11.1@2333.81,3197.48
  Top Layer w19.68: -185.66,3550 JP1.1@-100,3550 ; -185.66,3650 JP1.2@-100,3650 ; -100,3491.47 JP1.1@-100,3550 ; JP1.2@-100,3645.03 JP1.1@-100,3550 ; -100,3745.03 JP1.2@-100,3650 ; v1@-4.97,3550 JP1.1@-100,3550 ; v1@-4.97,3650 JP1.2@-100,3650 ; CN7.24@0,800 91.38,800 ; CN7.22@0,900 v1@83.34,900 ; 108.62,900 CN6.6@200,900 ; 116.66,800 CN6.7@200,800 ; U14.1@136.52,1716.18 155.52,1697.18 155.52,1642.26 C32.1@150.79,1637.54 ; v1(538.69,3107.91) 542.13,3104.47 C17.1@571.17,3104.47 ; v1(645.5,1655.76) 659.28,1641.98 C34.1@659.28,1641 ; v1(747.76,341.79) 748.18,341.37 U18.2@748.18,302 ; CN3.3@1074.96,3708.25 v1@1074.96,3783.21 ; R38.1@1201.28,2878.68 1247.35,2878.68 T3.2@1257.49,2868.54 ; v1(1531.7,1043.84) 1570.38,1043.84 ; v1(1580,1558) 1612.72,1590.72 C35.1@1612.72,1604 ; v1(1647,1856) 1647,1873.28 R47.1@1649,1875.28 1652.59,1871.69 U15.5@1695.04,1871.69 ; U10.2@1819.84,2944.08 1901.73,2944.08 C21.1@1915.56,2957.91 ; C24.1@1985,2747.56 C25.1@2063,2747.56 ; 2314.34,3550 JP2.1@2400,3550 ; 2314.34,3650 JP2.2@2400,3650 ; CN10.22@2400,900 2468.25,900 ; 2400,3491.47 JP2.1@2400,3550 ; JP2.2@2400,3645.03 JP2.1@2400,3550 ; 2400,3745.03 JP2.2@2400,3650 ; 2495.03,3550 JP2.1@2400,3550 ; 2495.03,3650 JP2.2@2400,3650
  Top Layer w30: -182,2600 CN11.2@-100,2600 -100,2518 ; -182,2800 JP4.2@-100,2800 -100,2882
  GND w7.87: 815.26,1418.54 842.72,1391.08 ; 842.82,1464.01 875.96,1430.88 882.53,1430.88
  GND w9.84: v1@803.16,1479.97 v1(803.16,1480.35)
  GND w15: 888.19,1442.52 1000.05,1442.52 ; 935.24,1394.23 988.49,1394.23
  GND w19.68: -185.66,3550 JP1.1@-100,3550 ; -185.66,3650 JP1.2@-100,3650 ; -100,3491.47 JP1.1@-100,3550 ; JP1.2@-100,3645.03 JP1.1@-100,3550 ; -100,3745.03 JP1.2@-100,3650 ; v1@-4.97,3550 JP1.1@-100,3550 ; v1@-4.97,3650 JP1.2@-100,3650 ; CN7.24@0,800 91.38,800 ; CN7.24@0,816.66 CN7.22@0,900 v1@83.34,900 ; 108.62,900 CN6.6@200,900 ; 116.66,800 CN6.7@200,800 291.38,800 ; CN6.7@200,816.66 CN6.6@200,900 ; 283.34,900 CN6.6@200,900 ; CN3.3@1074.96,3708.25 v1@1074.96,3783.21 ; 2314.34,3550 JP2.1@2400,3550 ; 2314.34,3650 JP2.2@2400,3650 ; CN10.22@2400,900 2468.25,900 ; 2400,3491.47 JP2.1@2400,3550 ; JP2.2@2400,3645.03 JP2.1@2400,3550 ; 2400,3745.03 JP2.2@2400,3650 ; 2495.03,3550 JP2.1@2400,3550 ; 2495.03,3650 JP2.2@2400,3650
  GND w30: -182,2600 CN11.2@-100,2600 -100,2518 ; -182,2800 JP4.2@-100,2800 -100,2882
  POWER w9.84: 1485.44,1050.23 1515.95,1050.23
  POWER w11.02: 781.11,1295.81 808.87,1323.56
  POWER w11.81: 114.68,1050.39 311.68,1050.39 ; 114.68,1250.39 311.68,1250.39 ; 114.93,1150.14 311.93,1150.14 ; 311.68,1250.68 314,1253 ; 1536.06,1610 1537.75,1608.31 1635,1608.31
  POWER w13.78: 906,923 914.25,931.25 948.25,931.25 949,932
  POWER w19.68: -185.66,3550 JP1.1@-100,3550 ; -185.66,3650 JP1.2@-100,3650 ; -100,3491.47 JP1.1@-100,3550 ; JP1.2@-100,3645.03 JP1.1@-100,3550 ; -100,3745.03 JP1.2@-100,3650 ; v1@-4.97,3550 JP1.1@-100,3550 ; v1@-4.97,3650 JP1.2@-100,3650 ; CN7.24@0,800 91.38,800 ; CN7.24@0,816.66 CN7.22@0,900 v1@83.34,900 ; CN6.6@200,900 CN6.7@200,800 291.38,800 ; CN3.3@1074.96,3708.25 v1@1074.96,3783.21 ; 2314.34,3550 JP2.1@2400,3550 ; 2314.34,3650 JP2.2@2400,3650 ; CN10.22@2400,900 2468.25,900 ; 2400,3491.47 JP2.1@2400,3550 ; JP2.2@2400,3645.03 JP2.1@2400,3550 ; 2400,3745.03 JP2.2@2400,3650 ; 2495.03,3550 JP2.1@2400,3550 ; 2495.03,3650 JP2.2@2400,3650
  POWER w30: -182,2600 CN11.2@-100,2600 -100,2518 ; -182,2800 JP4.2@-100,2800 -100,2882 ; 300,821 300,700 455,700 ; 1105,700 1321,700
  Bottom Layer w11.81: v1@199.71,3040.96 199.71,3052.79 224.53,3077.61 U21.5@233.95,3077.61 306.69,3077.61 306.98,3077.9 355.7,3077.9 U21.4@356,3077.61 368.22,3065.39 368.22,3047.08 v1(352.66,3031.53) ; C54.1@320.78,3419.35 324.91,3423.48 324.91,3428.31 343.96,3447.37 v1(343.96,3454.72) ; 918.15,922.15 922,926 929,926
  Bottom Layer w13.78: 911.24,929.07 911.52,929.35 953.35,929.35 969,945 ; 2155.95,2538.1 2160.27,2538.1 2197,2574.83
  Bottom Layer w15.75: R71.1@1962,846 1984.6,846 1994.33,836.27 1995.03,836.27 v1(2003.6,827.7)
  Bottom Layer w19.68: -185.66,3550 JP1.1@-100,3550 ; -185.66,3650 JP1.2@-100,3650 ; -100,3491.47 JP1.1@-100,3550 ; JP1.2@-100,3645.03 JP1.1@-100,3550 ; -100,3745.03 JP1.2@-100,3650 ; v1@-4.97,3550 JP1.1@-100,3550 ; v1@-4.97,3650 JP1.2@-100,3650 ; CN7.24@0,816.66 CN7.22@0,900 ; CN6.7@200,816.66 CN6.6@200,900 ; 283.34,900 CN6.6@200,900 ; 291.38,800 CN6.7@200,800 CN6.6@200,900 ; CN3.3@1074.96,3708.25 v1@1074.96,3783.21 ; 2314.34,3550 JP2.1@2400,3550 ; 2314.34,3650 JP2.2@2400,3650 ; CN10.22@2400,900 2468.25,900 ; 2400,3491.47 JP2.1@2400,3550 ; JP2.2@2400,3645.03 JP2.1@2400,3550 ; 2400,3745.03 JP2.2@2400,3650 ; 2495.03,3550 JP2.1@2400,3550 ; 2495.03,3650 JP2.2@2400,3650
  Bottom Layer w30: -182,2600 CN11.2@-100,2600 -100,2518 ; -182,2800 JP4.2@-100,2800 -100,2882 ; 1060.7,700 1321,700
  other v1: 234,-86 103,-84 2071.17,-84 2404.73,-82.84 -114.85,-82.74 2202,-59.97 422,-52 2488.49,-44.84 970.83,-10 -177.65,-3.7 1068,1 521,5.79 436.91,23 2199,56 435,67.66 579,76.34 1103.16,99.25 1269.23,105 536.06,116.53 2200,123 971.13,126.04 872.83,133 -177.06,147.08 2035,155 642,170 2482.98,176.81 575,203 912,203.63 1110.53,218.93 961,228 386,244 800,257 683,258 994,269.68 576.32,289 662.61,317 976,316.72 818.9,321 -193.2,343.25 643,353 2484.75,358.6 1005,363.57 106,375 829,382.18 1005.31,439.3 829,442 656,449.5 803,457.06 991.6,466 911.67,476 698.03,484 801.39,489 102,527 911.61,547 953,553 694.79,567 227,569 797.43,577.72 653,597 837,631 1841,645 -195.17,646.3 1968.82,648 726,650 1300.57,667 896,682 650.81,693 786.6,705 944,722 1910.29,725 1981.81,727 2465.26,727.89 1042,755 302,772 660,772 760,775 839.57,777 2089,781 2151.96,782 75.99,799.35 1624.46,823.93 1491,846 1305.67,846.31 1421,847 1200.75,848 1037,851 1514.46,862.1 75.11,899.84 -195.47,932.42 1976,942.45 653,949.46 523.72,951.42 740.76,951.42 2464.48,964.9 1573,1035 77,1071 1574,1100.05 1898.12,1100.07 1461.52,1105.35 535.93,1116.28 624.61,1125.14 -200,1129 580.81,1130.24 1095.48,1130.35 1328.35,1160.66 1058.23,1216.02 989.38,1237.83 1216.91,1259.78 2465.07,1293.3 1808,1302.42 1898.24,1303.58 455,1316 1569.33,1324.87 521,1328.29 1664.76,1331.67 1209.84,1351.77 996,1417 741.44,1453.68 1004.44,1470 1903,1478.9 2193.4,1481 2464.67,1496.59 1543,1520 1592.47,1535.18 808.57,1551.81 933.77,1556.53 1709.9,1558.23 980.35,1566.36 955,1583.8 650.2,1603.78 1789.87,1605 1895.5,1621.69 1937,1623 985.34,1625.33 1693.85,1629 1615.81,1635 2174.73,1637 325.1,1654.04 857.72,1656.08 982.53,1674.38 2464.67,1674.64 860,1692.49 825.27,1722 915,1723 984,1728 1091.51,1727.19 1573.07,1729 1814,1739 1960.39,1753.19 1639,1759.6 147.45,1775.79 1565.57,1793.7 2464.08,1795.61 177.37,1810.27 280.32,1851.51 329.04,1851.91 1920.5,1860.86 2018.59,1860.86 2199.23,1864.6 428,1904 456,1911 2160.94,1928 2465.95,1938.52 2009,1959 1955.5,1961 2099,1961.7 1906.7,1964 367,1969 1601.14,1971 1792,1978.94 2227,1981.9 2352.2,1981.9 2425.27,1981.9 363.88,2011.79 -198,2015 231.96,2019.25 1643.38,2041.23 1762.86,2044.09 2116.76,2076.02 2498,2121 1822,2124.56 -118,2133 2375.16,2173 234.46,2185.67 2185,2187 1984.87,2194 2077,2219.65 2202,2219.65 388.27,2231 1382.81,2231 1009.88,2242 2340.14,2243.71 1091.52,2246 868.5,2247.07 1188,2249 1691,2250.91 1474.85,2253 1786.47,2252.32 1858,2254 1284.44,2256.63 236,2290.22 354.32,2328 1186,2329 2102.7,2330 -57.09,2339 -160,2341 2481,2342.83 117.92,2345.51 1091.52,2348.95 1476,2355.46 1703.75,2356.63 1291.35,2359 1388.29,2364 1583.18,2366.57 1898.16,2366.57 891.65,2368 344.73,2373 27,2380 1000.68,2384 751.48,2390 1983.57,2392.43 453,2399 1185.05,2412 576,2412.75 1077.53,2413 1468.95,2416.94 1583.68,2418 1784.21,2419 1697.04,2420.12 2221,2420.78 234.65,2429.72 97,2454 2155.15,2454 2278,2483 1977.96,2495.25 1932.96,2497.25 -149,2502 21,2519 1955.96,2518.25 2476,2532 1955.96,2540.25 1983.96,2559.09 -187,2575 111,2585 2387,2585 1985.15,2586.65 2208,2611.61 364.28,2612.34 1575.99,2612.64 1707,2613 1275,2620 1784,2637 228.36,2653 1397,2653 1724.91,2654.66 2279,2664.75 361.82,2666.47 1699,2701.47 1595,2711.07 2021,2713.75 1157,2716 2448,2724.76 91,2729 1848,2728.84 2456.4,2758.01 1782.93,2760.35 154.09,2778 -184.47,2788 2034.46,2794 2453,2805.85 1337,2809 1750.34,2808.8 1438,2812 1540,2813 1848.53,2815.05 232,2833.33 2310.15,2840.39 2179.3,2842.79 73,2881 1597.74,2880.35 1778,2881.09 -71,2891.93 -164.17,2925.63 1105.52,2926.51 179,2927.57 84,2929.37 1888.89,2945.31 1599.71,2961.55 1871.46,2968.05 227.17,2981.24 -169.09,2983 1632.98,2989.35 1300.7,3001.32 1774.42,3019.62 1890.66,3025.43 1260.44,3041.18 1606.5,3043.15 200.3,3043.54 1691.35,3044.33 1850.3,3049.84 2168.14,3069.96 2212,3070.71 1390.95,3092.66 1800.6,3097.77 1912.11,3102.6 1504.73,3104.07 1637.84,3104.66 2286.09,3107 2430,3114 318.79,3123.17 -154.52,3128.88 908.08,3132.32 317.63,3143.84 -125.88,3165.1 514.38,3175.17 623.33,3174.74 2220.22,3179.56 2301.62,3179.47 2150.83,3180.94 2187.64,3180.94 1499.26,3182.71 -129.91,3215.19 695,3225.3 2407.49,3238.03 2498.73,3242.66 1338.29,3243.84 1241.35,3245.56 1546.11,3245.71 1799.55,3245.61 1170.87,3246.2 1491.98,3247.08 1747.49,3246.2 1905.27,3248.17 497.74,3248.76 1274.52,3249.19 1607.96,3253.25 2142.63,3256.63 -159.84,3261.26 877.17,3262.14 2282.19,3261.45 1364.08,3266.67 234.65,3276.22 346.27,3277.5 498.04,3282.03 1387.21,3290.1 1038,3293.05 1600.7,3295.31 1811.52,3296.49 1546.27,3301.32 1491.15,3302.4 2047.84,3304.25 1952.17,3307.22 2433.18,3310.67 1996.96,3314.29 1858.77,3322.58 1171.76,3327.01 1241.94,3326.81 1272.15,3326.42 2245.93,3329.2 2321.23,3329.59 2489.53,3329.2 517,3347.13 2083.08,3353.97 1273.73,3356.34 1339.08,3359.78 2140.91,3367.49 1386.72,3383.8 1529.04,3383.99 1595.68,3387.05 504.73,3391.18 724.22,3399.25 2324.12,3407.62 1715.76,3420.02 1792.13,3421.4 -111.02,3435.18 577.47,3437.83 2476.98,3437.44 1517.82,3438.32 269.3,3446.49 -193.3,3464.51 2013.39,3468.54 2326.39,3468.25 1793.71,3471.2 2145.87,3473.46 612.02,3475.92 718.22,3477.2 103,3480 381.75,3484.25 1601.68,3494.21 2049.22,3501.71 2190.85,3506.73 2235.54,3508.8 -0.39,3548.17 717.88,3550.04 791.44,3549.55 2482.78,3549.84 609,3561 1268.71,3571.76 1416.51,3572.68 127,3575.28 1700.01,3576.81 545,3578.38 909.95,3578.58 954.14,3578.38 275.2,3580.06 1088.29,3579.98 2112.8,3579.76 1783.77,3580.65 762.31,3582.12 822.15,3581.63 2226.68,3590.69 658,3623 1204.63,3640.98 744,3642.06 -1.96,3650.73 623.82,3652 1319.1,3657.81 1437.7,3658.99 2149.61,3660.86 1683.08,3661.45 2082.09,3661.85 548.87,3664 1555.13,3670.21 802.52,3688.57 -180.01,3692.75 2127.27,3716.87 1601.09,3717.66 2472.94,3734.98 675,3739.76 546,3755 797,3758 1294,3763.32 -31.39,3764.41 2278.06,3765.1 1723.14,3767.95 2085.54,3769.53 1555.72,3778.29 238.69,3781.04 871.66,3783.99 1075.2,3787.93
GNDDetect: CN4.11 R26.2 U6.4 | length 652.8
  Top Layer w11.81: R26.2@-155,3063.28 -53.72,3063.28 CN4.11@-53,3064 ; U6.4@329.44,3201.68 v1(329.44,3227.5)
  POWER w11.81: v1(-127.06,3062.93) 37.51,3227.5 v1(329.44,3227.5)
I2C_SCL: R48.1 SB5.2 U15.1 | length 110.2
  Top Layer w5.98: SB5.2@1765.32,1792.52 1765.12,1792.71 U15.1@1765.12,1846.1 1812.71,1846.1 R48.1@1819,1839.81
I2C_SDA: R49.1 SB4.2 U15.6 | length 106.3
  Top Layer w5.98: R49.1@1650,1793.28 1699.56,1793.28 1700.28,1792.56 1700.28,1840.86 U15.6@1695.04,1846.1
MCU.MCO: C9.2 R19.2 TP2.1 | length 101.8
  Top Layer w5.98: R19.2@1240.19,3192.55 TP2.1@1341.94,3192.55
MCU.SWCLK: CN2.4 CN4.6 CN4.9 R34.2 SB13.1 U6.1 U16.61 | length 3691.4
  Top Layer w5.98: CN4.9@-53,3114 13.67,3114 27.07,3127.4 27.07,3204.57 36.51,3214 CN4.6@107,3214 172.14,3214 210.98,3252.84 U6.1@262.5,3252.84 278.21,3252.84 287.7,3262.34 v1(287.7,3273.27) ; v1(324,3503.41) CN2.4@324,3623 ; v1(372.94,2973.56) 372.94,2939.14 439.7,2872.38 980.62,2872.38 983.77,2869.23 ; R34.2@983.77,2954.57 983.77,2869.23 ; U16.61@1387,1608.26 1387,1705 1436.38,1754.38 1436.38,2051.38 1526,2141 1526,2419 1228.16,2716.84 1228.16,2796.78 1209.94,2815 1038,2815 983.77,2869.23
  POWER w5.98: v1@287.7,3270.87 v1(287.7,3273.27) ; v1(324,3503.41) 372.94,3454.47 v1(372.94,3229.47) v1(372.94,2973.56)
  Bottom Layer w5.98: v1(287.7,3273.27) 287.7,3259.09 297.89,3248.91 353.5,3248.91 v1(372.94,3229.47) ; v1(1437,1781) 1460.32,1781 SB13.1@1476.32,1765
MCU.SWDIO: CN2.2 CN4.4 R14.2 R35.2 SB3.1 U6.5 U16.58 | length 3722.9
  Top Layer w5.98: CN4.4@107,3264 194.86,3264 227.16,3296.3 301.78,3296.3 313.29,3284.78 v1(313.29,3273.36) 313.29,3255.16 315.61,3252.84 U6.5@329.42,3252.84 401.83,3252.84 414.28,3240.39 414.28,3037.64 525.5,2926.42 v1(778.26,2926.42) 779.41,2927.57 R35.2@779.41,2954.54 ; CN2.2@224,3623 224,3536.58 313.68,3446.9 313.68,3427.99 R14.2@296.94,3411.25 ; v1(1020.87,2926.51) 1020.87,2876.71 1063.3,2834.28 1218.08,2834.28 1247.98,2804.38 1247.98,2715.38 1538.98,2424.38 1538.98,2125.98 1465,2052 v1(1464,2052) ; U16.58@1464.76,1490.15 1550.15,1490.15 v1(1560,1500) ; v1(1517,1726) 1507.98,1735.02 1507.98,1839.78 1528.38,1860.18 1528.38,1992.38 v1(1565,2029) ; 1525,1849.2 SB3.1@1531.8,1856
  POWER w5.98: v1(313.29,3273.36) v1(313.29,3447.48) ; v1@783.57,2926.51 v1(1020.87,2926.51) ; v1(1464,2052) 1487,2029 v1(1565,2029) v1@1562.2,2031.8 ; v1(1560,1500) v1@1561,1501
  Bottom Layer w5.98: v1(1517,1726) 1498,1707 1498,1516 1514,1500 v1(1560,1500)
MCU.SWO: CN2.6 CN4.8 R17.2 U6.3 | length 1235.1
  Top Layer w5.98: CN4.8@107,3164 210.03,3164 247.7,3201.66 U6.3@262.5,3201.66 262.5,3182.33 272.74,3172.08 367.13,3172.08 v1(393.81,3145.41) ; R17.2@296.94,3363.25 v1@393.81,3363.25 ; CN2.6@374,3673 374,3712 391,3729 468,3729 497.35,3699.65 497.35,3560.77 448,3511.42 448,3381.79 429.73,3363.52 v1(393.81,3363.52)
  POWER w5.98: v1(393.81,3145.41) 393.81,3362.14 395.18,3363.52 v1@395.18,3364.41
NetB2_1: B2.1 R69.1 R70.2 | length 136
  Top Layer w5.98: B2.1@2174.73,2352.67 2210.05,2388 v1(2227,2388)
  Bottom Layer w5.98: v1(2227,2388) 2244.47,2370.53 R70.2@2246.47,2370.53 R69.1@2276.47,2400.53
NetB2_2: B2.2 C41.2 R57.2 R70.1 SB10.1 U13.1 | length 3410.3
  Top Layer w5.98: v1(390,2291) v1(994,2291) ; v1(419,1282) 432.81,1295.81 v1(573.94,1295.81) ; v1(2121.06,2291) 2146.77,2265.29 2157.71,2265.29 U13.1@2161.3,2261.7 2247,2347.4 2269.6,2347.4 v1(2287,2330)
  Top Layer w7.99: R57.2@551.58,1202.79 555.62,1206.83 v1(574.42,1206.83) C41.2@599.32,1206.83 651.88,1206.83 SB10.1@658.67,1200.04
  POWER w5.98: v1(574.42,1206.83) v1@574.42,1295.33 ; v1(994,2291) v1(2121.06,2291)
  Bottom Layer w5.98: v1(390,2291) 323.85,2224.85 323.85,2218.19 323.81,2218.15 323.81,1960.1 419,1864.91 v1(419,1282) ; R70.1@2271.53,2345.47 v1(2287,2330)
NetB2_3: B2.3 R68.1 R69.2 | length 183.4
  Top Layer w5.98: B2.3@2273.48,2274.73 v1(2300.76,2302)
  Top Layer w8: B2.3@2252.67,2274.73 B2.3@2273.48,2274.73
  Bottom Layer w5.98: v1(2300.76,2302) 2312,2313.24 2312,2365 R69.2@2301.53,2375.47 R69.2@2302.02,2375.47
  Bottom Layer w8: R69.2@2302.02,2375.47 R68.1@2331.02,2404.47
NetB2_4: B2.4 R67.1 R68.2 | length 130.8
  Top Layer w5.98: v1(2314.12,2492) 2314.12,2492.07 B2.4@2347.33,2525.27
  Bottom Layer w5.98: R68.2@2305.97,2429.53 2334.97,2458.53 R67.1@2335.41,2458.53 2314.12,2479.82 v1(2314.12,2492)
NetB2_6: B2.6 R67.2 | length 84.2
  Top Layer w5.98: v1(2377,2416.94) 2394.89,2416.94 B2.6@2425.27,2447.33
  Bottom Layer w5.98: R67.2@2360.47,2433.47 v1(2377,2416.94)
NetC10_2: C10.2 U8.4 | length 58.5
  Top Layer w5.98: C10.2@1534.69,3210.57 U8.4@1593.16,3210.57
NetC12_2: C12.2 C15.2 D1.2 D2.2 U8.1 U8.3 | length 407.3
  Top Layer w11.81: U8.1@1680.07,3135.47 1645.72,3135.47 1635.58,3145.61 1635.58,3200.53 1645.32,3210.27 U8.3@1680.07,3210.27
  Top Layer w19.68: U8.1@1680.07,3135.47 1680.36,3135.77 C12.2@1798.96,3135.77 1861.37,3135.77 D2.2@1863.33,3137.73 D1.2@1863.33,3208.73
NetC18_2: C18.2 U10.4 | length 78.3
  Top Layer w11.81: C18.2@1678.55,3008.9 1726.68,3008.9 1733.22,3002.35 U10.4@1733.22,2981.48
NetC24_2: C24.2 R44.2 U12.1 U12.5 | length 215.2
  Top Layer w5.98: C24.2@1985,2692.44 1985.66,2692.44 v1(2011.42,2666.67) U12.1@2011.42,2649.35 ; v1@2008.67,2568.44 v1(2011.62,2568.44) U12.5@2011.62,2582.81
  Top Layer w7.99: R44.2@1941.72,2694.28 1943.56,2692.44 C24.2@1985,2692.44
  POWER w5.98: v1(2011.42,2666.67) 2011.42,2567.92 2011.62,2568.11 v1(2011.62,2568.44)
NetC27_2: C27.2 TP3.1 U12.6 | length 213
  Top Layer w5.98: TP3.1@1937.8,2429 1963.09,2429 2034.52,2500.43 C27.2@2034.52,2528.25 ; C27.2@2037.96,2528.25 2037.96,2531.46 2042,2535.5 U12.6@2042,2585.49
NetC36_2: C36.2 R52.1 X2.2 | length 127.2
  Top Layer w7.99: C36.2@629.34,1571.69 689.77,1571.69 X2.2@689.97,1571.89 724.81,1571.89 R52.1@747.15,1549.55
NetC37_2: C37.2 R53.1 X2.1 | length 119.8
  Top Layer w8: C37.2@624.22,1509.58 743.13,1509.58 R53.1@743.75,1508.96
NetC38_2: C38.2 R54.1 X3.1 | length 171.5
  Top Layer w5.51: C38.2@614.16,1422.79 666.25,1422.79 666.25,1418.33 X3.1@666.88,1417.7 ; X3.1@666.25,1417.07 666.25,1411.36 687.03,1390.58 726.39,1390.58 744.79,1408.98 R54.1@744.79,1422.58
NetC39_2: C39.2 R55.1 X3.3 | length 178.9
  Top Layer w5.51: C39.2@621.17,1370.22 C39.2@621.17,1365 621.17,1345.03 631.11,1335.09 700.51,1335.09 707.59,1342.16 X3.3@707.59,1363.92 ; X3.3@710.54,1363.92 X3.3@710.54,1369.22 ; X3.3@710.54,1369.64 X3.3@710.54,1369.22 ; R55.1@743.3,1369.22 X3.3@710.54,1369.22
NetCN1_A5: CN1.A5 R16.1 | length 136.5
  Top Layer w11.81: CN1.A5@1934.8,3505.75 1934.8,3395.45 R16.1@1953.31,3376.94
NetCN1_B5: CN1.B5 R10.1 | length 141.8
  Top Layer w11.81: v1(1829.44,3475.53) 1829.83,3475.14 R10.1@1829.83,3455.35 ; v1@1882.68,3534.29 1885.59,3537.19 CN1.B5@1885.59,3572.68
  POWER w11.81: v1(1829.44,3475.53) 1829.44,3478.09 v1(1885.54,3534.19)
NetCN2_5: CN2.5 SB1.2 | length 231.3
  Top Layer w5.98: CN2.5@374,3623 374,3530.89 412.21,3492.68 SB1.2@412.21,3407.52
NetCN5_8: CN5.8 SB17.1 | length 158.5
  Bottom Layer w15.75: SB17.1@1941.54,1560 CN5.8@2100,1560
NetCN6_1: CN6.1 R51.2 | length 319.5
  Top Layer w15.75: v2(294.89,1622.87) R51.2@294.89,1649.15
  Bottom Layer w15.75: CN6.1@200,1400 200,1580.94 241.94,1622.87 v2(294.89,1622.87)
NetCN7_15: CN7.15 SB3.2 | length 2126.5
  Top Layer w5.98: CN7.15@-100,1200 -49.67,1250.33 40.79,1250.33 72.94,1282.49 72.94,1412.94 136.02,1476.02 325.65,1476.02 538.77,1689.13 538.77,1767.71 555.37,1784.31 870.4,1784.31 905.9,1819.81 v1(1002,1819.81) ; SB3.2@1579.62,1856 1571.54,1847.91 1581,1838.45 v1(1581,1826)
  POWER w5.98: v1(1002,1819.81) 1204.62,1819.81 1242.81,1858 1479.75,1858 1511.75,1826 v1(1581,1826)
